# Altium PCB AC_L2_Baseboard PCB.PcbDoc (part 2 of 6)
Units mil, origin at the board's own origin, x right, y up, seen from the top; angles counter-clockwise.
Board outline 7290 x 7055 mil, 4 copper layers (Top Layer, Layer 1, Layer 2, Bottom Layer), stack 70.356 mil thick; 510 components, 285 nets, 1364 pads, 522 vias.
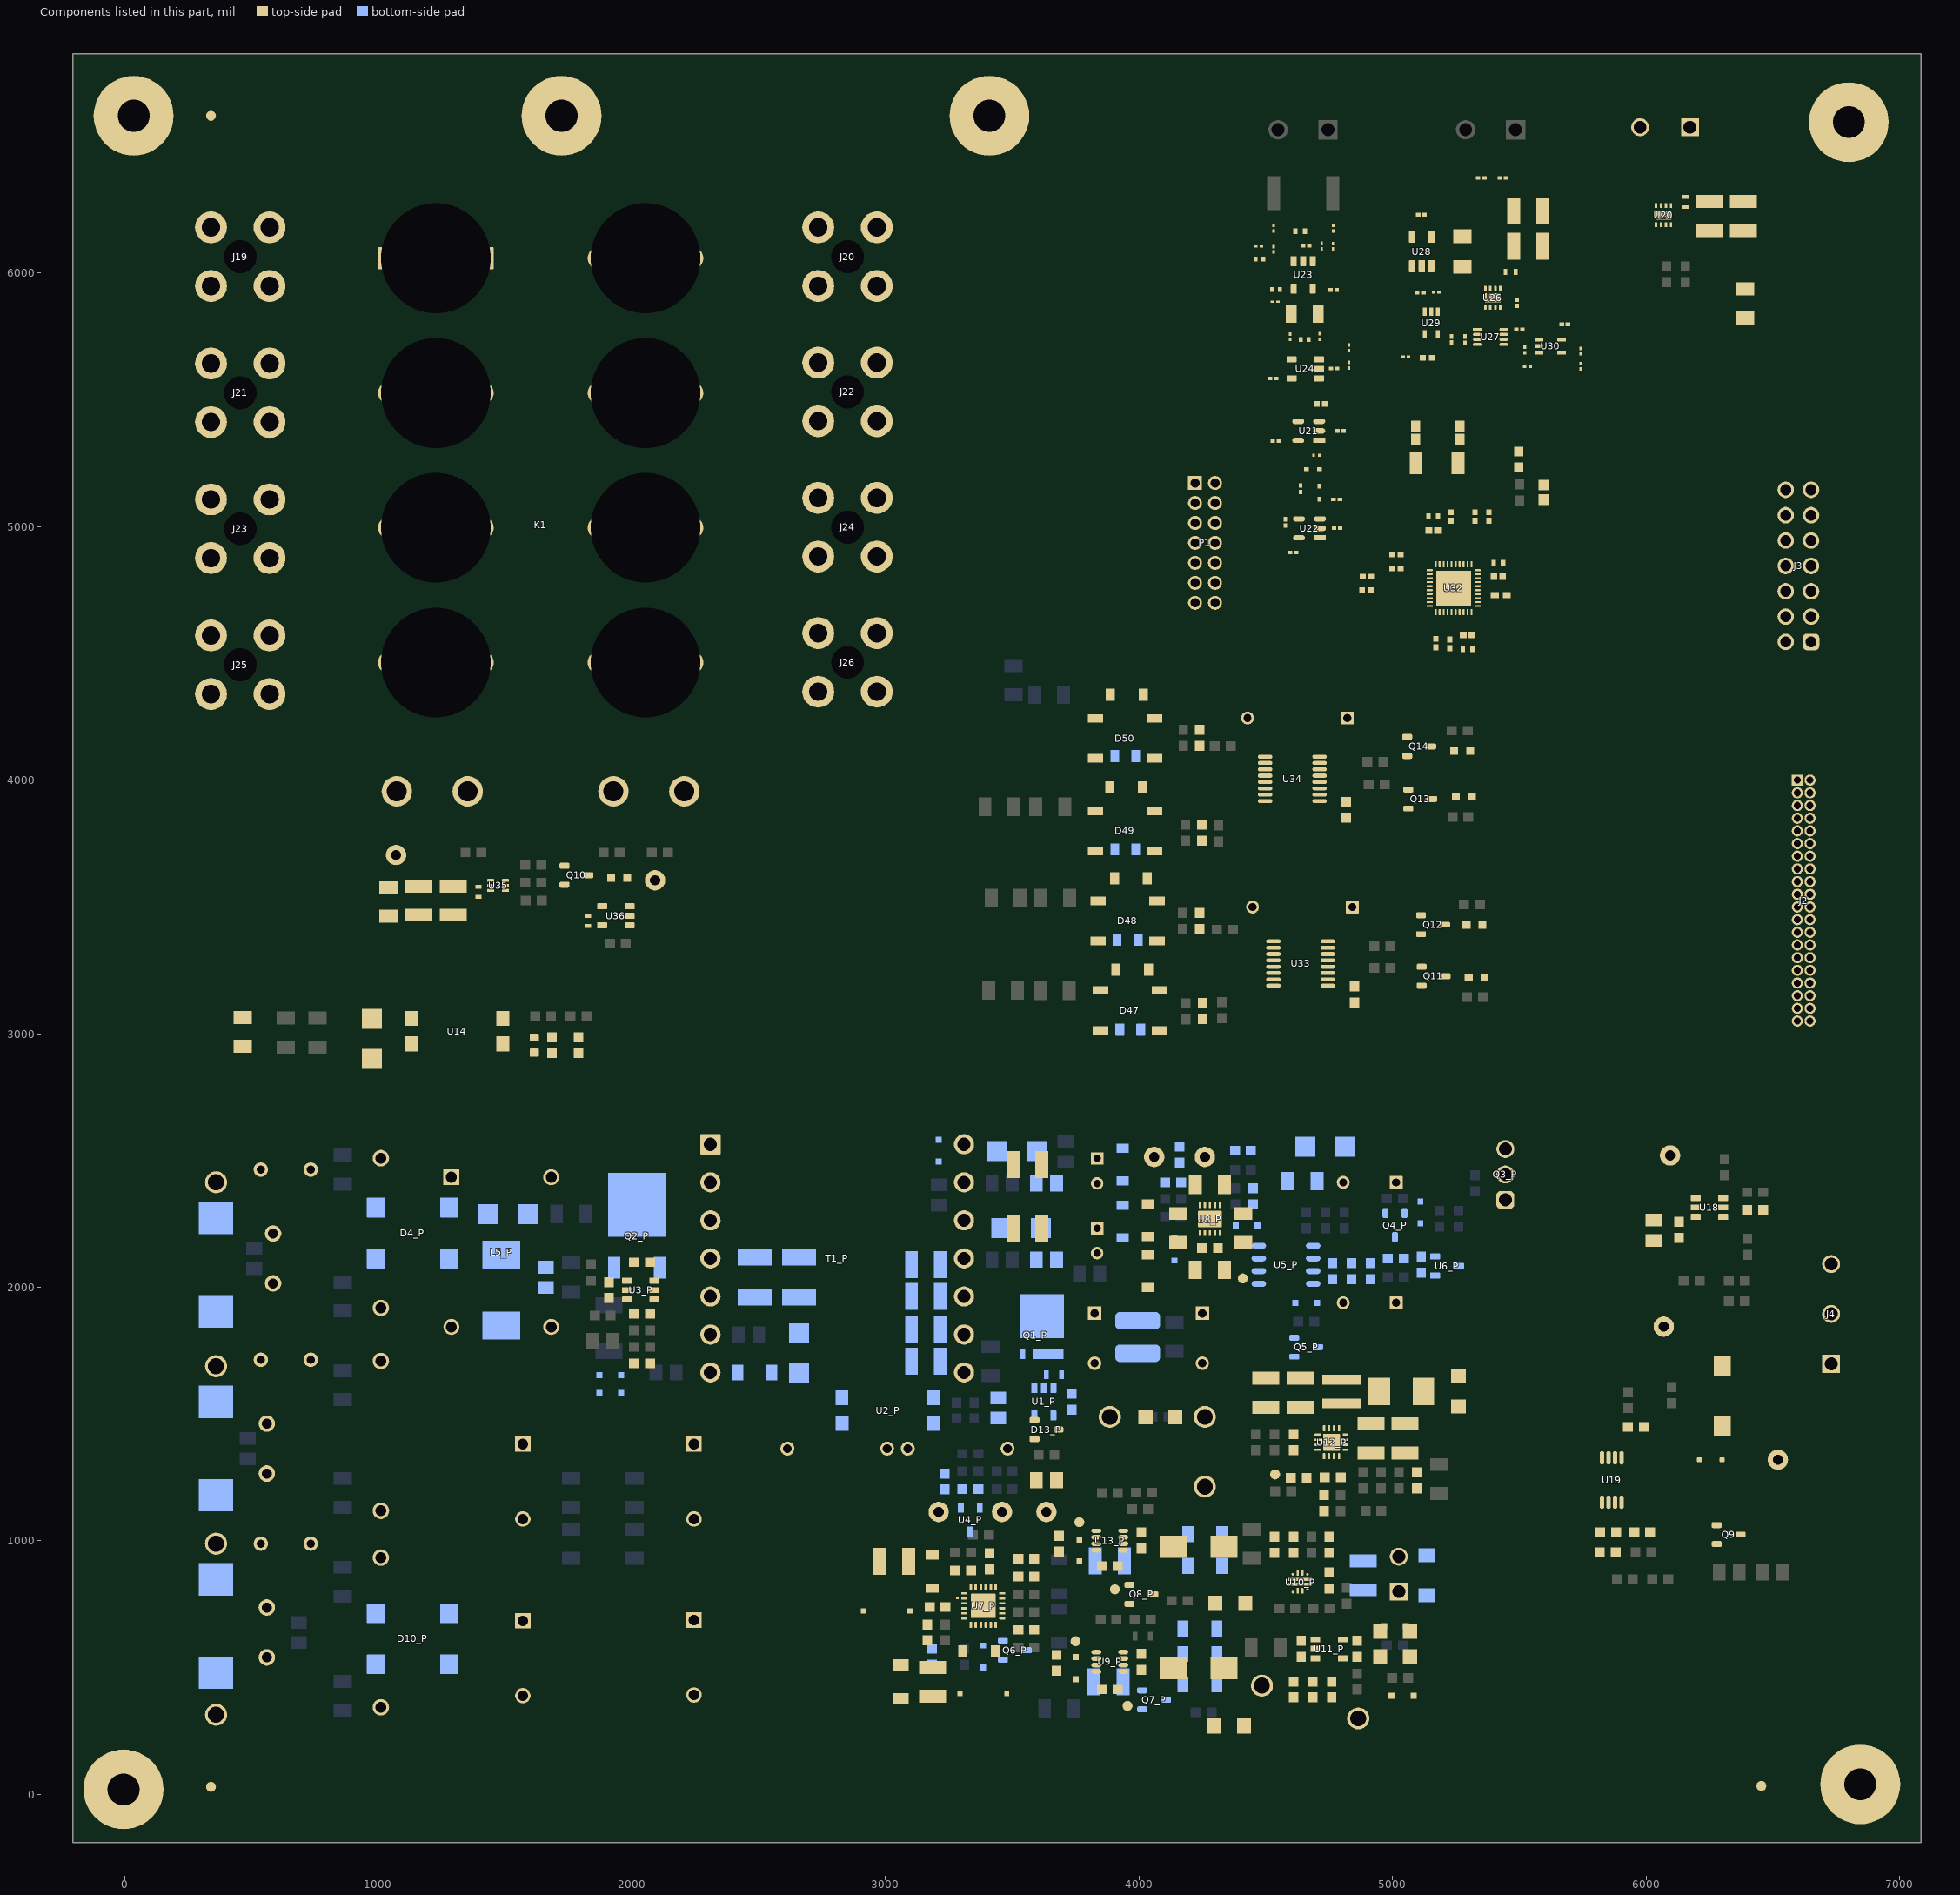
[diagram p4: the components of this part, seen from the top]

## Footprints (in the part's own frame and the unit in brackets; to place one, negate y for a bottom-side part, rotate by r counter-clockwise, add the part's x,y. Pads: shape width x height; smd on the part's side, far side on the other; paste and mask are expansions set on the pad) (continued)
B32672P_1800x850x1450 [mm] "TH, 2-Leads, Body 18x8.5mm, PinSpacing 15mm"
  round 1.65 hole 1.1: 1(-7.5,0) 2(7.5,0)
  silkscreen extent -9,-4.25 9,4.25, body extent -9,-4.25 9,4.25, height 14.5
CAPC1005X56X25NL10T15 [mm] "Chip Capacitor, 2-Leads, Body 1.00x0.50mm, IPC Medium Density"
  rect 0.68x0.64 smd: 1(-0.44,0) 2(0.44,0)
  body extent -0.55,-0.3 0.55,0.3, height 0.56
CE_Mark_5mm [mil] "Minimum text height for CE Mark"
  silkscreen extent -138,-98 138,98
Chemi-Con_630X1100 [mm] "TH, 2-Leads, Dia 6.3mm, Pin Spacing 2.5mm"
  rect 1.25x1.25 hole 0.75: 1(-1.25,0)
  round 1.25 hole 0.75: 2(1.25,0)
  silkscreen extent -3.4,-3.4 3.4,3.4, body extent -3.4,-3.4 3.41,3.4, height 12.51
Chemi-Con_1000x2000 [mm] "TH, 2-Leads, Body 10x20mm, Pin Spacing 5mm"
  rect 1.35x1.35 hole 0.85: 1(-2.5,0)
  round 1.35 hole 0.85: 2(2.5,0)
  silkscreen extent -5.25,-5.25 5.25,5.25, body extent -5.25,-5.25 5.25,5.25, height 21.5
D0008A_N [mm] "SOIC, 8-Leads, Body 4.9x3.9mm, Pitch 1.27mm, IPC Medium Density"
  oval 1.45x0.6 smd: 1(-2.725,1.905) 2(-2.725,0.635) 3(-2.725,-0.635) 4(-2.725,-1.905) 5(2.725,-1.905) 6(2.725,-0.635) 7(2.725,0.635) 8(2.725,1.905)
  silkscreen extent -3.3,-2.5 0.9,2.5, body extent -3,-2.45 3,2.45, height 1.63
DBQ0016A_N [mm] "SOP, 16-Leads, Body 4.9x3.9mm, Pitch 0.635mm, IPC Medium Density"
  oval 1.45x0.4 smd: 1(-2.725,2.222) 2(-2.725,1.587) 3(-2.725,0.952) 4(-2.725,0.317) 5(-2.725,-0.318) 6(-2.725,-0.953) 7(-2.725,-1.588) 8(-2.725,-2.223) 9(2.725,-2.222) 10(2.725,-1.587) 11(2.725,-0.952) 12(2.725,-0.317) 13(2.725,0.318) 14(2.725,0.953) 15(2.725,1.588) 16(2.725,2.223)
  silkscreen extent -3.35,-2.5 1.1,2.68, body extent -3.01,-2.45 3.01,2.45, height 1.63
DBV0005A_M [mm] "SOT23, 5-Leads, Body 2.9x1.6mm, Pitch 0.95mm, Lead Span 2.8mm, IPC Low Density"
  rrect15% 1.2x0.65 smd: 1(-1.475,0.95) 2(-1.475,0) 3(-1.475,-0.95) 4(1.475,-0.95) 5(1.475,0.95)
  silkscreen extent -1.63,-1.55 0.38,1.55, body extent -1.42,-1.46 1.42,1.46, height 1.09
DBV0005A_N [mm] "SOT23, 5-Leads, Body 2.9x1.6mm, Pitch 0.95mm, Lead Span 2.8mm, IPC Medium Density"
  rrect17% 1x0.6 smd: 1(-1.375,0.95) 2(-1.375,0) 3(-1.375,-0.95) 4(1.375,-0.95) 5(1.375,0.95)
  silkscreen extent -0.25,-1.55 0.25,1.55, body extent -1.42,-1.46 1.42,1.46, height 1.09
DBV0006A_N [mm] "SOT23, 6-Leads, Body 2.9x1.6mm, Pitch 0.95mm, Lead Span 2.8mm, IPC Medium Density"
  rrect17% 1x0.6 smd: 1(-1.375,0.95) 2(-1.375,0) 3(-1.375,-0.95) 4(1.375,-0.95) 5(1.375,0) 6(1.375,0.95)
  silkscreen extent -1.68,-1.55 0.5,1.55, body extent -1.42,-1.46 1.42,1.46, height 1.12
DBZ0003A_N [mm] "SOT23, 3-Leads, Body 2.9x1.3mm, Pitch 0.95mm, Lead Span 2.4mm, IPC Medium Density"
  rrect17% 1x0.6 smd: 1(-1.2,0.95) 2(-1.2,-0.95) 3(1.2,0)
  silkscreen extent 0.2,-1.5 0.7,1.5, body extent -1.26,-1.46 1.26,1.46, height 0.98
DCK0005A_N [mm] "SOT353, 5-Leads, Body 2x1.3mm, Pitch 0.65mm, Lead Span 2.1mm, IPC Medium Density"
  rrect25% 0.85x0.4 smd: 1(-1.125,0.65) 2(-1.125,0) 3(-1.125,-0.65) 4(1.125,-0.65) 5(1.125,0.65)
  silkscreen extent -1.48,-1.02 0.55,1.1, body extent -1.14,-1 1.14,1, height 0.95
DDF0008A_N [mm] "SOT-23-THN-8, IPC Medium Density"
  oval 1x0.45 smd: 1(-1.35,0.975) 2(-1.35,0.325) 3(-1.35,-0.325) 4(-1.35,-0.975) 5(1.35,-0.975) 6(1.35,-0.325) 7(1.35,0.325) 8(1.35,0.975)
  body extent -1.41,-1.45 1.41,1.45, height 0.9
DGK0008A_N [mm] "TSOP, 8-Leads, Body 3x3mm, Pitch 0.65mm, IPC Medium Density"
  oval 1.35x0.45 smd: 1(-2.225,0.975) 2(-2.225,0.325) 3(-2.225,-0.325) 4(-2.225,-0.975) 5(2.225,-0.975) 6(2.225,-0.325) 7(2.225,0.325) 8(2.225,0.975)
  silkscreen extent -2.75,-1.55 0.95,1.55, body extent -2.45,-1.5 2.45,1.5, height 0.96
DRL0006A-MFG [mm]
  rrect33% 0.67x0.3 smd paste+0 mask+0: 1(-0.74,0.5) 2(-0.74,0) 3(-0.74,-0.5) 4(0.74,-0.5) 5(0.74,0) 6(0.74,0.5)
  silkscreen extent -1.9,-1.05 0.65,1.05, body extent -1.17,-1.1 1.17,1.1, height 0.25
DSC0010J [mm] "WSON-10"
  rrect42% 0.6x0.24 smd: 1(-1.4,1) 2(-1.4,0.5) 3(-1.4,0) 4(-1.4,-0.5) 5(-1.4,-1) 6(1.4,-1) 7(1.4,-0.5) 8(1.4,0) 9(1.4,0.5) 10(1.4,1)
  rrect12% 1.65x2.4 smd paste-1 mask-2: 11(0,0)
  Top Layer region: -0.375,-1.65 -0.375,-1.2 -0.775,-1.2 -0.794,-1.196 -0.81,-1.185 -0.821,-1.169 -0.825,-1.15 -0.825,-1.15 -0.825,1.15 -0.821,1.169 -0.81,1.185 -0.794,1.196 -0.775,1.2 -0.775,1.2 -0.375,1.2 -0.375,1.65 -0.371,1.669 -0.36,1.685 -0.344,1.696 -0.325,1.7 -0.325,1.7 -0.325,1.7 -0.175,1.7 -0.175,1.7 -0.156,1.696 -0.14,1.685 -0.129,1.669 -0.125,1.65 -0.125,1.65 -0.125,1.2 0.125,1.2 0.125,1.65 0.129,1.669 0.14,1.685 0.156,1.696 0.175,1.7 0.175,1.7 0.175,1.7 0.325,1.7 0.325,1.7 0.344,1.696 0.36,1.685 0.371,1.669 0.375,1.65 0.375,1.65 0.375,1.2 0.775,1.2 0.794,1.196 0.81,1.185 0.821,1.169 0.825,1.15 0.825,1.15 0.825,-1.15 0.821,-1.169 0.81,-1.185 0.794,-1.196 0.775,-1.2 0.775,-1.2 0.375,-1.2 0.375,-1.65 0.371,-1.669 0.36,-1.685 0.344,-1.696 0.325,-1.7 0.325,-1.7 0.175,-1.7 0.156,-1.696 0.14,-1.685 0.129,-1.669 0.125,-1.65 0.125,-1.65 0.125,-1.2 -0.125,-1.2 -0.125,-1.65 -0.129,-1.669 -0.14,-1.685 -0.156,-1.696 -0.175,-1.7 -0.175,-1.7 -0.325,-1.7 -0.344,-1.696 -0.36,-1.685 -0.371,-1.669 -0.375,-1.65
  body extent -1.5,-1.5 1.5,1.5, height 0.8
DSG0008A-MFG [mm]
  rrect40% 0.5x0.25 smd paste+0 mask+0: 1(-0.95,0.75) 2(-0.95,0.25) 3(-0.95,-0.25) 4(-0.95,-0.75) 5(0.95,-0.75) 6(0.95,-0.25) 7(0.95,0.25) 8(0.95,0.75)
  rrect11% 0.9x1.6 smd paste-1000 mask+0: 9(0,0)
  silkscreen extent -1.87,-1.39 1,1.4, body extent -1.3,-1.15 1.3,1.15, height 0.25
FCC_disclaimer [mil]
Fiducial10-20 [mm]
  round 1 smd mask+0.5: 1(0,0)
  Top Layer keep-out circle w1.178: c0,0 r0.5
FP-502-01-MFG [mm]
  rect 0.48x0.4 smd paste+0 mask+0: 1(-0.66,0) 2(0.66,0)
  silkscreen extent -1.63,-0.45 0.05,0.45, body extent -1,-0.55 1,0.55, height 0.25
FP-750320029_PTH14_32MM25_27MM05-MFG [mm]
  rrect5% 2.02x2.02 hole 1.32 paste-1000 mask+0: 1(-12.7,11.43)
  round 2.02 hole 1.32 paste-1000 mask+0: 2(-12.7,7.62) 3(-12.7,3.81) 4(-12.7,0) 5(-12.7,-3.81) 6(-12.7,-7.62) 7(-12.7,-11.43) 8(12.7,-11.43) 9(12.7,-7.62) 10(12.7,-3.81) 11(12.7,0) 12(12.7,3.81) 13(12.7,7.62) 14(12.7,11.43)
  silkscreen extent -16.85,-13.52 16.12,13.52, body extent -16.22,-13.62 16.22,13.62, height 0.25
FP-ABS10-MFG [mm]
  rect 1.3x2.2 smd paste+0 mask+0: 1(-2.1,0) 2(2.1,0)
  silkscreen extent -1.07,-0.95 1.07,0.95, body extent -2.85,-1.2 2.85,1.2, height 0.25
FP-AC0402-0_37-IPC_B [mil]
  rect 24.23x22.54 smd paste+0 mask+0: 1(-16.87,0) 2(16.87,0)
  silkscreen extent -29,-27 29,27, body extent -35,-17 35,17, height 10
FP-AHER4191_PTH_RELAY_35MM0_58MM0-MFG [mm]
  rrect5% 2.2x11.6 hole 11 slot 1.6 at 0 deg paste-1000 mask+0: 1(26.5,10.5)
  rrect100% 2.2x11.6 hole 11 slot 1.6 at 0 deg paste-1000 mask+0: 2(13,10.5) 3(-0.5,10.5) 4(-14,10.5) 9(-14,-10.5) 10(-0.5,-10.5) 11(13,-10.5) 12(26.5,-10.5)
  round 3.05 hole 2 paste-1000 mask+0: 5(-26.9,14.4) 6(-26.9,7.3) 7(-26.9,-7.3) 8(-26.9,-14.4)
  silkscreen extent -29.25,-17.75 29.97,17.75, body extent -29.35,-17.85 29.35,17.85, height 0.25
FP-AQ4023-01FTG-C_SOD323-MFG [mm]
  rrect22% 0.49x0.45 smd paste+0 mask+0: 1(-1.14,0) 2(1.14,0)
  silkscreen extent -0.9,-0.7 0.9,0.7, body extent -1.49,-0.8 1.49,0.8, height 0.25
FP-BSC220N20NSFDATMA1_TSON-8-MFG [mm]
  rrect10% 3.08x1 smd paste-1000 mask-1000: 1-2-3(-0.635,-2.75)
  rrect19% 0.54x1 smd paste-1000 mask+0: 4(1.905,-2.75)
  rrect2% 4.45x4.4 smd paste-1000 mask-1000: 5-6-7-8(0,1.05)
  silkscreen extent -2.5,-4.02 2.5,-1.53, body extent -2.5,-3.01 2.5,3.01, height 1.1
FP-C0201-AB-MFG [mm]
  rect 0.36x0.32 smd paste+0 mask+0: 1(-0.28,0) 2(0.28,0)
  silkscreen extent -0.3,-0.55 0.3,0.55
FP-C0603-030-0_03-MFG [mm]
  rect 0.25x0.3 smd paste+0 mask+0: 1(-0.275,0) 2(0.275,0)
  silkscreen extent -0.32,-0.53 0.32,0.53, body extent -0.5,-0.27 0.5,0.27, height 0.25
FP-C1608-080-0_1-IPC_B [mil]
  rect 44.53x35.91 smd paste+0 mask+0: 1(-25.22,0) 2(25.22,0)
  silkscreen extent -47,-34 47,34, body extent -57,-28 57,28, height 10
FP-CC0603KRX7R7BB224_0603-MFG [mm]
  rrect13% 0.8x0.9 smd paste+0 mask+0: 1(-0.75,0) 2(0.75,0)
  silkscreen extent -0.85,-0.85 0.85,0.85, body extent -1.43,-0.82 1.43,0.82, height 0.25
FP-CRCW1206-e3-IPC_A [mil]
  rect 53.39x73.16 smd paste+0 mask+0: 1(-60.08,0) 2(60.08,0)
  silkscreen extent -19,-31 19,31, body extent -106,-56 106,56, height 10
FP-DBV0005A-IPC_C [mm]
  rect 1.205x0.532 smd paste+0 mask+0: 1(-1.05,0.95)
  rrect100% 1.205x0.532 smd paste+0 mask+0: 2(-1.05,0) 3(-1.05,-0.95) 4(1.05,-0.95) 5(1.05,0.95)
  silkscreen extent -2.45,-1.45 0.05,1.45, body extent -1.75,-1.55 1.75,1.55, height 0.25
FP-DCU0008A-IPC_C [mm]
  rect 0.86x0.297 smd paste+0 mask+0: 1(-1.326,0.75)
  rrect100% 0.86x0.297 smd paste+0 mask+0: 2(-1.326,0.25) 3(-1.326,-0.25) 4(-1.326,-0.75) 5(1.326,-0.75) 6(1.326,-0.25) 7(1.326,0.25) 8(1.326,0.75)
  silkscreen extent -2.46,-1 0.4,1, body extent -1.86,-1.1 1.86,1.1, height 0.25
FP-ERA3A-IPC_B [mil]
  rect 41.53x39.61 smd paste+0 mask+0: 1(-28.57,0) 2(28.57,0)
  silkscreen extent -49,-36 49,36, body extent -59,-30 59,30, height 10
FP-FTSH-120-01-L-D_HDR40-MFG [mm]
  rrect9% 1.12x1.12 hole 0.71 paste-1000 mask+0: 1(-12.065,-0.635)
  round 1.12 hole 0.71 paste-1000 mask+0: 2(-12.065,0.635) 3(-10.795,-0.635) 4(-10.795,0.635) 5(-9.525,-0.635) 6(-9.525,0.635) 7(-8.255,-0.635) 8(-8.255,0.635) 9(-6.985,-0.635) 10(-6.985,0.635) 11(-5.715,-0.635) 12(-5.715,0.635) 13(-4.445,-0.635) 14(-4.445,0.635) 15(-3.175,-0.635) 16(-3.175,0.635) 17(-1.905,-0.635) 18(-1.905,0.635) 19(-0.635,-0.635) 20(-0.635,0.635) 21(0.635,-0.635) 22(0.635,0.635) 23(1.905,-0.635) 24(1.905,0.635) 25(3.175,-0.635) 26(3.175,0.635) 27(4.445,-0.635) 28(4.445,0.635) 29(5.715,-0.635) 30(5.715,0.635) 31(6.985,-0.635) 32(6.985,0.635) 33(8.255,-0.635) 34(8.255,0.635) 35(9.525,-0.635) 36(9.525,0.635) 37(10.795,-0.635) 38(10.795,0.635) 39(12.065,-0.635) 40(12.065,0.635)
  silkscreen extent -12.77,-2.37 12.77,1.78, body extent -12.87,-1.88 12.87,1.88, height 0.25
FP-GRM155-0_1-MFG [mm]
  rect 0.4x0.5 smd paste+0 mask+0: 1(-0.4,0) 2(0.4,0)
  silkscreen extent -0.53,-0.65 0.53,0.65, body extent -0.7,-0.38 0.7,0.38, height 0.25
FP-GRM155-0_2-MFG [mm]
  rect 0.45x0.6 smd paste+0 mask+0: 1(-0.475,0) 2(0.475,0)
  silkscreen extent -0.6,-0.64 0.6,0.65, body extent -0.8,-0.45 0.8,0.45, height 0.25
FP-GRT033-0_03-IPC_B [mil]
  rect 17.88x14.28 smd paste+0 mask+0: 1(-11.98,0) 2(11.98,0)
  silkscreen extent -21,-23 21,23, body extent -27,-13 27,13, height 10
FP-IPD95R2K0P7ATMA1_DPAK-MFG [mm]
  rrect8% 1.2x2.2 smd paste-1000 mask+0: 1(-2.28,-5.12) 3(2.28,-5.12)
  rrect2% 5.8x6.4 smd paste-1000 mask+0: 4(0,1.18)
  silkscreen extent -3.35,-3.1 3.35,3.1, body extent -3.27,-5.79 3.27,4.15, height 2.42
FP-PHVL-3R9V255-R_RADIAL-MFG [mm]
  rrect8% 1.3x1.3 hole 0.8 paste-1000 mask+0: 1(-2.65,0)
  round 1.3 hole 0.8 paste-1000 mask+0: 2(2.65,0)
  silkscreen extent -10.9,-5.75 10.9,5.75, body extent -11,-5.85 11,5.85, height 0.25
FP-Q07E1D471KN0B0S0N0_RADIAL-MFG [mm]
  rrect8% 1.3x1.3 hole 0.8 paste-1000 mask+0: 1(-5,0)
  round 1.3 hole 0.8 paste-1000 mask+0: 2(5,0)
  silkscreen extent -3.5,-2.5 3.5,2.5, body extent -5.75,-2.6 5.75,2.6, height 0.25
FP-RC0805FR-070RL_0805-MFG [mm]
  rrect11% 0.9x1.2 smd paste+0 mask+0: 1(-1.05,0) 2(1.05,0)
  silkscreen extent -0.23,-0.67 0.23,0.67, body extent -1,-0.63 1,0.63, height 0.6
FP-RG1005-IPC_B [mil]
  rect 23.18x22.54 smd paste+0 mask+0: 1(-18.25,0) 2(18.25,0)
  silkscreen extent -30,-27 30,27, body extent -36,-17 36,17, height 10
FUSE_0443 [mm] "LITTELFUSE"
  rect 3.25x3.43 smd: 1(-4.675,0) 2(4.675,0)
  silkscreen extent -2.7,-1.7 2.7,1.7, body extent -5.05,-1.56 5.05,1.56, height 3.12
HW_1600x2500 [mm] "TH, 2-Leads, Dia 16mm, Pin Spacing 7.5mm"
  rect 1.55x1.55 hole 1.05: 1(-3.75,0)
  round 1.55 hole 1.05: 2(3.75,0)
  silkscreen extent -8.25,-8.25 8.25,8.25, body extent -8.19,-8.24 8.23,8.24, height 27.01
IEC_HighVoltage_Medium [mil]
  silkscreen extent -217,-176 217,200
Keystone5000 [mil] "For Keystone 500x miniature loop terminals"
  round 80 hole 40: 1(0,0)
  silkscreen extent -52,-52 52,52, body extent -49,-49 49,49, height 182
Keystone5001 [mil] "For Keystone 500x miniature loop terminals"
  round 80 hole 40: 1(0,0)
  silkscreen extent -52,-52 52,52, body extent -49,-49 49,49, height 182
Keystone5003 [mil] "For Keystone 500x miniature loop terminals"
  round 80 hole 40: 1(0,0)
  silkscreen extent -52,-52 52,52, body extent -49,-49 49,49, height 182
Keystone5010 [mil] "Keystone Multipurpose loops"
  round 87 hole 63: 1(0,0)
  silkscreen extent -70,-70 70,70, body extent -63,-63 63,62, height 319
Keystone5011 [mil] "Keystone Multipurpose loops"
  round 87 hole 63: 1(0,0)
  silkscreen extent -70,-70 70,70, body extent -63,-63 63,62, height 319
Keystone5012 [mil] "Keystone Multipurpose loops"
  round 87 hole 63: 1(0,0)
  silkscreen extent -70,-70 70,70, body extent -63,-63 63,62, height 319
KX_1000x700 [mm] "TH, 2-Leads, Dia 10mm, Lead Spacing 10mm"
  round 1.4 hole 0.9: 1(-5,0) 2(5,0)
  silkscreen extent -5,-3.5 5,3.5, body extent -5.32,-3.5 5.33,3.5, height 12.99
Label_650x200 [mil] "Thermal Transfer Label"
  round 1 on Mech14: 0(0,0)
  silkscreen extent -325,-100 325,100, body extent -325,-100 325,100, height 1
MICRODIP_4 [mm] "FAIRCHILD"
  rect 1.55x0.85 smd: 1(-2.95,2) 2(-2.95,-2) 3(2.95,-2) 4(2.95,2)
  silkscreen extent -2.62,-2.6 2.3,2.6, body extent -3.4,-2.57 3.4,2.57, height 1.45
MOLEX-87831-1420_V [mm] "Connector, 14-Leads, Body 16.65x6.3mm, Pitch 2mm"
  rect 1.4x1.4 hole 0.9: 1(-6,-1)
  round 1.4 hole 0.9: 2(-6,1) 3(-4,-1) 4(-4,1) 5(-2,-1) 6(-2,1) 7(0,-1) 8(0,1) 9(2,-1) 10(2,1) 11(4,-1) 12(4,1) 13(6,-1) 14(6,1)
  silkscreen extent -8.32,-3.92 8.32,3.15, body extent -8.32,-3.15 8.33,3.15, height 6.2
N04C [mm] "FAIRCHILD"
  rect 1.3x1.5 smd mask+0.065: 1(-4.587,1.27) 2(-4.612,-1.27) 3(4.588,-1.27) 4(4.613,1.27)
  silkscreen extent -3.56,-2.3 3.56,2.72, body extent -5.08,-2.3 5.08,2.29, height 3.87
Net-Tie_10mil [mil] "10mil net tie, no solder mask opening, no solder paste"
  rect 10x10 smd paste-5 mask-5: 1(-10,0) 2(10,0)
  Top Layer region: -6,5 6,5 6,-5 -6,-5
Net-Tie_0805_HV_NoOverlay [mil] "0805_HV pads tied by 10mil copper trace which can be cut.  An 0805 part can be placed on pads."
  rect 50x63 smd paste-25: 1(-40,0) 2(40,0)
  Top Layer lines w10: 16,0 -16,0
  Top Layer keep-out lines w1: 22,-30.91 22,30.91 ; 14.96,-30.91 -14.96,-30.91 ; -22,-30.91 -22,30.91 ; 14.96,30.91 -14.96,30.91
"NY PMS 440 0025 PH" [mm] "4-40 nylon screw and mounting hole"
  round 8 hole 3.2: 1(0,0)
  body extent -3.3,-3.3 3.3,3.3, height 2.69
RESC0603X28X15LL05T05 [mm] "Chip Resistor, 2-Leads, Body 0.60x0.30mm, IPC High Density"
  rect 0.35x0.25 smd: 1(-0.275,0) 2(0.275,0)
  body extent -0.33,-0.17 0.32,0.18, height 0.28
RESC0603X28X15NL05T05 [mm] "Chip Resistor, 2-Leads, Body 0.60x0.30mm, IPC Medium Density"
  rect 0.45x0.35 smd: 1(-0.325,0) 2(0.325,0)
  body extent -0.33,-0.17 0.33,0.18, height 0.28
RESC1005X40X25NL05T10 [mm] "Chip Resistor, 2-Leads, Body 1.00x0.50mm, IPC Medium Density"
  rect 0.6x0.55 smd: 1(-0.425,0) 2(0.425,0)
  body extent -0.53,-0.27 0.53,0.28, height 0.4
RGE0024B [mm] "QFN, 24-Leads, Body 4x4mm, Pitch 0.5mm, Thermal Pad 2.45x2.45mm, TI Recommended"
  rrect40% 0.6x0.25 smd: 1(-1.9,1.25) 2(-1.9,0.75) 3(-1.9,0.25) 4(-1.9,-0.25) 5(-1.9,-0.75) 6(-1.9,-1.25) 13(1.9,-1.25) 14(1.9,-0.75) 15(1.9,-0.25) 16(1.9,0.25) 17(1.9,0.75) 18(1.9,1.25)
  rrect40% 0.25x0.6 smd: 7(-1.25,-1.9) 8(-0.75,-1.9) 9(-0.25,-1.9) 10(0.25,-1.9) 11(0.75,-1.9) 12(1.25,-1.9) 19(1.25,1.9) 20(0.75,1.9) 21(0.25,1.9) 22(-0.25,1.9) 23(-0.75,1.9) 24(-1.25,1.9)
  rrect9% 1.08x1.08 on Top Paste: 25(-0.64,-0.64) 25(-0.64,0.64) 25(0.64,-0.64) 25(0.64,0.64)
  rrect4% 2.45x2.45 smd paste-1.225: 25(0,0)
  silkscreen extent -2.22,-2.22 2.22,2.22, body extent -2,-2 2,2, height 1
RPW0010A-MFG [mm]
  round 0.27 smd paste-1000 mask+0: 1(-1.05,0.7) 10(0.75,0.7)
  rrect40% 0.6x0.25 smd paste+0 mask+0: 2(-0.9,0.225) 3(-0.9,-0.225) 8(0.9,-0.225) 9(0.9,0.225)
  round 0.255 smd paste-1000 mask+0: 4(-0.75,-0.75) 7(0.75,-0.75)
  rrect33% 0.3x2.4 smd paste-1000 mask+0: 5(-0.25,0) 6(0.25,0)
  Top Layer region: -0.85,0.85 -0.85,1.15 -0.843,1.175 -0.825,1.193 -0.8,1.2 -0.8,1.2 -0.65,1.2 -0.631,1.196 -0.615,1.185 -0.604,1.169 -0.6,1.15 -0.6,1.15 -0.6,0.6 -0.604,0.581 -0.615,0.565 -0.631,0.554 -0.65,0.55 -0.65,0.55 -1.15,0.55 -1.169,0.554 -1.185,0.565 -1.196,0.581 -1.2,0.6 -1.2,0.6 -1.2,0.8 -1.193,0.825 -1.175,0.843 -1.15,0.85 -1.15,0.85
  Top Layer region: -0.85,-0.85 -0.85,-1.15 -0.846,-1.169 -0.835,-1.185 -0.819,-1.196 -0.8,-1.2 -0.8,-1.2 -0.65,-1.2 -0.631,-1.196 -0.615,-1.185 -0.604,-1.169 -0.6,-1.15 -0.6,-1.15 -0.6,-0.6 -0.604,-0.581 -0.615,-0.565 -0.631,-0.554 -0.65,-0.55 -0.65,-0.55 -1.15,-0.55 -1.169,-0.554 -1.185,-0.565 -1.196,-0.581 -1.2,-0.6 -1.2,-0.6 -1.2,-0.8 -1.196,-0.819 -1.185,-0.835 -1.169,-0.846 -1.15,-0.85 -1.15,-0.85
  Top Layer region: 0.85,-0.85 0.85,-1.15 0.846,-1.169 0.835,-1.185 0.819,-1.196 0.8,-1.2 0.8,-1.2 0.65,-1.2 0.631,-1.196 0.615,-1.185 0.604,-1.169 0.6,-1.15 0.6,-1.15 0.6,-0.6 0.604,-0.581 0.615,-0.565 0.631,-0.554 0.65,-0.55 0.65,-0.55 1.15,-0.55 1.169,-0.554 1.185,-0.565 1.196,-0.581 1.2,-0.6 1.2,-0.6 1.2,-0.8 1.196,-0.819 1.185,-0.835 1.169,-0.846 1.15,-0.85 1.15,-0.85
  Top Layer region: 0.85,0.85 0.85,1.15 0.846,1.169 0.835,1.185 0.819,1.196 0.8,1.2 0.8,1.2 0.65,1.2 0.631,1.196 0.615,1.185 0.604,1.169 0.6,1.15 0.6,1.15 0.6,0.6 0.604,0.581 0.615,0.565 0.631,0.554 0.65,0.55 0.65,0.55 1.15,0.55 1.169,0.554 1.185,0.565 1.196,0.581 1.2,0.6 1.2,0.6 1.2,0.8 1.196,0.819 1.185,0.835 1.169,0.846 1.15,0.85 1.15,0.85
  silkscreen extent -1.87,-1.58 1.05,1.58, body extent -1.3,-1.3 1.3,1.3, height 0.25
RSB0040B [mm] "WQFN-40"
  rrect50% 0.6x0.2 smd: 1(-2.4,1.8) 2(-2.4,1.4) 3(-2.4,1) 4(-2.4,0.6) 5(-2.4,0.2) 6(-2.4,-0.2) 7(-2.4,-0.6) 8(-2.4,-1) 9(-2.4,-1.4) 10(-2.4,-1.8) 21(2.4,-1.8) 22(2.4,-1.4) 23(2.4,-1) 24(2.4,-0.6) 25(2.4,-0.2) 26(2.4,0.2) 27(2.4,0.6) 28(2.4,1) 29(2.4,1.4) 30(2.4,1.8)
  rrect50% 0.2x0.6 smd: 11(-1.8,-2.4) 12(-1.4,-2.4) 13(-1,-2.4) 14(-0.6,-2.4) 15(-0.2,-2.4) 16(0.2,-2.4) 17(0.6,-2.4) 18(1,-2.4) 19(1.4,-2.4) 20(1.8,-2.4) 31(1.8,2.4) 32(1.4,2.4) 33(1,2.4) 34(0.6,2.4) 35(0.2,2.4) 36(-0.2,2.4) 37(-0.6,2.4) 38(-1,2.4) 39(-1.4,2.4) 40(-1.8,2.4)
  rrect3% 3.5x3.5 smd paste-1.75: 41(0,0)
  body extent -2.5,-2.5 2.5,2.5, height 0.8
RTE0016C_NV [mm] "Texas Insturments"
  rrect42% 0.6x0.24 smd: 1(-1.4,0.75) 2(-1.4,0.25) 3(-1.4,-0.25) 4(-1.4,-0.75) 9(1.4,-0.75) 10(1.4,-0.25) 11(1.4,0.25) 12(1.4,0.75)
  rrect42% 0.24x0.6 smd: 5(-0.75,-1.4) 6(-0.25,-1.4) 7(0.25,-1.4) 8(0.75,-1.4) 13(0.75,1.4) 14(0.25,1.4) 15(-0.25,1.4) 16(-0.75,1.4)
  rrect6% 1.55x1.55 on Top Paste: 17(0,0)
  rrect6% 1.68x1.68 smd paste-0.85: 17(0,0)
  silkscreen extent -1.72,-1.73 1.72,1.73, body extent -1.57,-1.57 1.58,1.58, height 0.81
S153 [mm] "EPCOS"
  round 1.45 hole 0.8: 1(-2.5,0) 2(2.5,0)
  silkscreen extent -4.2,-3 4.2,3, body extent -4.23,-3 4.23,3, height 12.99
SMA [mm] "Molded Diode, 2-Leads, Body 4.3x2.6mm, IPC Medium Density, based on OnSemi component dimensions and land pattern"
  rect 2x2 smd: 1(-2,0) 2(2,0)
  silkscreen extent -3.66,-1.57 2.79,1.57, body extent -2.6,-1.3 2.6,1.3, height 2.42
SMA_Bi [mm] "SMD, 2-Leads, Body 4.275x2.575mm"
  rect 1.4x1.64 smd: 1(-2.015,0) 2(2.015,0)
  silkscreen extent -2.3,-1.45 2.3,1.45, body extent -2.52,-1.45 2.52,1.45, height 2.65
SMB [mil] "Molded Diode, 2-Leads, Body 5.4x3.6mm, IPC Medium Density, based on OnSemi component dimensions"
  rect 85x107.99 smd: 1(-87.01,0) 2(87.01,0)
  silkscreen extent -155,-82 125,82, body extent -106,-71 106,71, height 91
SMC [mil] "Molded Diode, 2-Leads, Body 6.9x5.8mm, IPC Medium Density, based on OnSemi component dimensions and land patterns"
  rect 110x150 smd: 1(-140.49,0) 2(140.49,0)
  silkscreen extent -221,-123 189,124, body extent -156,-116 156,116, height 91
SOD-123 [mm] "On Semi recommended land pattern"
  rect 0.915x1.22 smd: 1(-1.637,0) 2(1.637,0)
  silkscreen extent -2.74,-1.17 2.03,1.17, body extent -1.93,-0.9 1.93,0.9, height 1.35
SOD-123FL [mm] "Copied from SOD-123"
  rect 0.915x1.22 smd: 1(-1.637,0) 2(1.637,0)
  silkscreen extent -2.74,-1.16 1.68,1.16, body extent -1.9,-0.9 1.9,0.9, height 1
SOD-323 [mm] "NXP recommended land pattern"
  rect 0.6x0.6 smd paste-0.05: 1(-1.1,0) 2(1.1,0)
  silkscreen extent -2.06,-0.86 1.53,0.86, body extent -1.3,-0.67 1.3,0.68, height 1.1
SOT-23 [mm] "SOT23, 3-Leads, Body 2.9x1.3mm, Pitch 0.95mm, Lead Span 2.5mm, IPC Medium Density"
  rrect50% 1x0.6 smd: 1(-1.2,0.95) 2(-1.2,-0.95) 3(1.2,0)
  silkscreen extent -1.63,-1.5 0.7,1.5, body extent -1.16,-1.45 1.21,1.45, height 1
TBS4 [mm] "Micro Commercial Components"
  rrect6% 1.8x2 smd: 1(-3.675,2.55) 2(-3.675,-2.55) 3(3.675,-2.55) 4(3.675,2.55)
  silkscreen extent -3.8,-3.45 3.8,3.45, body extent -4.3,-3.35 4.3,3.35, height 1.51
TO-220FP [mm] "FM, Body 10.4x4.6mm, Pitch 2.55mm"
  rrect50% 1.8x1.8 hole 1.3: 1(-2.55,0)
  round 1.8 hole 1.3: 2(0,0) 3(2.55,0)
  silkscreen extent -5.1,-1.5 5.08,3, body extent -5.09,-1.5 5.09,3, height 19.41
TP_SM_1MM [mm] "1mm Test Point, SMT"
  round 1 smd paste-0.5: 1(0,0)
WE-HC4 [mm] "Wurth Electronik recommended land pattern"
  rect 2.7x2.2 smd: 1(-2.55,0) 2(2.55,0)
  silkscreen extent -4.2,-4.2 4.2,4.2, body extent -3.65,-3.6 3.65,3.6, height 4
WE-PD2-S [mm] "WURTH"
  rrect50% 1.75x4.5 smd: 1(-1.625,0) 2(1.625,0)
  Top Layer region: -1.375,2.25 -0.75,2.25 -0.75,-2.25 -1.375,-2.25
  Top Layer region: 1.375,-2.25 0.75,-2.25 0.75,2.25 1.375,2.25
  silkscreen extent -0.4,-2.1 0.4,2.12, body extent -2.25,-2 2.25,2, height 3.18
WE-PD_7345_PlasticBase [mm] "SMD Inductor, 2-Leads, Body 7,3x7,3mm"
  rect 2x1.7 smd: 1(-3,0) 2(3,0)
  silkscreen extent -3.8,-3.8 3.8,3.8, body extent -3.65,-3.65 3.65,3.65, height 4.09
WE-TI_1014 [mm] "WURTH"
  round 1.65 hole 1: 1(-2.5,0) 2(2.5,0)
  silkscreen extent -5.3,-5.3 5.3,5.3, body extent -5.25,-5.25 5.25,5.25, height 14.5
WE-TPC-M1 [mm] "Wurth Elektronik recommended land pattern"
  rect 0.5x0.5 smd: 1(-2.35,0) 2(2.325,0)
  Top Layer region: -0.75,1.64 -1.005,1.504 -1.279,1.279 -1.504,1.005 -1.671,0.692 -1.774,0.353 -1.809,0 -1.774,-0.353 -1.671,-0.692 -1.504,-1.005 -1.279,-1.279 -1.005,-1.504 -0.75,-1.64 -0.75,-2.65 -2.75,-2.65 -2.75,2.65 -0.75,2.65
  Top Layer region: 0.75,1.64 1.005,1.504 1.279,1.279 1.504,1.005 1.671,0.692 1.774,0.353 1.809,0 1.774,-0.353 1.671,-0.692 1.504,-1.005 1.279,-1.279 1.005,-1.504 0.75,-1.64 0.75,-2.65 2.75,-2.65 2.75,2.65 0.75,2.65
  silkscreen extent -3,-3 3,3, body extent -2.5,-2.5 2.5,2.5, height 2
WEEE_Minimum [mil] "WEEElie bin"
  silkscreen extent -95,-172 99,104
WL-SMCW_GREEN [mm] "WURTH"
  rect 0.8x0.8 smd: 1(-0.8,0) 2(0.8,0)
  silkscreen extent -1.9,-0.8 1.2,0.8, body extent -0.85,-0.45 0.85,0.45, height 0.8
WL_SMCW_RED_1206 [mm] "SMD, 2-Leads, Body 3.2x1.6mm, Pitch 3mm"
  rect 1.4x1.5 smd: 1(-1.5,0) 2(1.5,0)
  silkscreen extent -2.9,-1.1 2.2,1.1, body extent -1.6,-0.85 1.6,0.85, height 0.78
Wurth_7446120047 [mm] "TH, 4-Leads, Body 18.5x13.5"
  rect 1.6x1.6 hole 1.1: 1(-5,7.5)
  round 1.6 hole 1.1: 2(5,7.5) 3(5,-7.5) 4(-5,-7.5)
  silkscreen extent -6.75,-9.25 6.75,9.75, body extent -6.74,-9.25 6.74,9.25, height 20.51
Wurth_61301421121 [mm] "Header, 2.54mm, 7x2, TH"
  rrect50% 1.65x1.65 hole 1.1: 1(-1.27,7.62)
  round 1.65 hole 1.1: 2(1.27,7.62) 3(-1.27,5.08) 4(1.27,5.08) 5(-1.27,2.54) 6(1.27,2.54) 7(-1.27,0) 8(1.27,0) 9(-1.27,-2.54) 10(1.27,-2.54) 11(-1.27,-5.08) 12(1.27,-5.08) 13(-1.27,-7.62) 14(1.27,-7.62)
  body extent -2.54,-8.89 2.54,8.89, height 8.55
Wurth_691101710002 [mm] "Terminal Block, 5 mm, 2x1, TH"
  rect 1.8x1.8 hole 1.3: 1(-2.5,0)
  round 1.8 hole 1.3: 2(2.5,0)
  silkscreen extent -5,-4.5 5.6,5, body extent -5.6,-4 5.6,5, height 12.5
Wurth_691101710003 [mm] "Terminal Block, 5 mm, 3x1, TH"
  rect 1.8x1.8 hole 1.3: 1(-5,0)
  round 1.8 hole 1.3: 2(0,0) 3(5,0)
  silkscreen extent -7.5,-4.5 8.1,5, body extent -8.1,-4 8.1,5, height 12.5
Wurth_691214110002 [mm] "Receptacle, 3.5mm, 2x1, TH"
  rect 1.8x1.8 hole 1.3: 1(-1.75,0)
  round 1.8 hole 1.3: 2(1.75,0)
  silkscreen extent -3.8,-3.4 3.5,4, body extent -3.9,-3.4 3.5,4, height 8.5
Wurth_WP-THRBU [mm] "Power Element Bush, M3, TH"
  round 3.2 hole 1.85: 1(-2.935,-2.935) 1(-2.935,2.935) 1(2.935,-2.935) 1(2.935,2.935)
  round 3.1 on Top Paste: ""(-2.935,-2.935) ""(-2.935,2.935) ""(2.935,-2.935) ""(2.935,2.935)
  round 3 hole 3.3 unplated mask+0.102: ""(0,0)
  silkscreen extent -3.5,-3.5 3.5,3.5, body extent -3.5,-3.5 3.5,3.5, height 3
XEL4030_310 [mm] "SMD, 2-Leads, Body 4x4mm, Pitch 2.37mm"
  rect 0.98x3.9 smd: 1(-1.185,0) 2(1.185,0)
  silkscreen extent -2.3,-2.3 2.3,2.3, body extent -2.15,-2.15 2.15,2.15, height 3.1

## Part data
C1_P C11_P: library part CMP-0008246-2, "CAP, CERM, 68 pF, 250 V, +/- 5%, C0G/NP0, 0805", Cap_Case=0805, Manufacturer=MuRata, Supplier Part Number 1=490-5540-1-ND, TempCo=C0G/NP0, Tolerance_%=5%, Value1=Unknown, Value2=250V, ValueDisplayed=68pF
C2_P C3_P: library part CMP-0009604-2, "CAP, CERM, 3300 pF, 300 V, +/- 20%, E, D10xT7mm", Cap_Case=10x7mm, Manufacturer=MuRata, Supplier Part Number 1=490-9516-1-ND, TempCo=E, Tolerance_%=20%, Value1=Unknown, Value2=300V, ValueDisplayed=3300pF
C4_P C12_P: library part CMP-0010399-1, "CAP, AL, 100 uF, 25 V, +/- 20%, TH", Cap_Case=6.3x11, Manufacturer=Wuerth, Tolerance_%=20%, Value1=Unknown, Value2=25V, ValueDisplayed=100uF
C5_P C10_P C21_P C22_P C23_P C24_P C43_P C54_P C64_P C74_P C79_P C80_P C83_P C84_P C87_P: library part CMP-0009224-2, "CAP, CERM, 22 uF, 25 V, +/- 20%, X5R, 1210", Cap_Case=1210, Manufacturer=Wuerth, TempCo=X5R, Tolerance_%=20%, Value1=Unknown, Value2=25V, ValueDisplayed=22uF
C6_P C7_P: library part CMP-0009326-2, "CAP, CERM, 0.1 uF, 1000 V, +/- 10%, X7R, 1812", Cap_Case=1812, Manufacturer=Kemet, Supplier Part Number 1=399-9854-1-ND, TempCo=X7R, Tolerance_%=10%, Value1=Unknown, Value2=1000V, ValueDisplayed=0.1uF
C8_P: library part CMP-0008251-2, "CAP, CERM, 1000 pF, 250 V, +/- 10%, X7R, 0805", Cap_Case=0805, Manufacturer=Wuerth, TempCo=X7R, Tolerance_%=10%, Value1=Unknown, Value2=250V, ValueDisplayed=1000pF
C9_P C15_P C20_P: library part CMP-0860409-1, "CAP, Film, 0.1 µF, 1000 VDC,+/- 10%, TH", Cap_Case=18x8.5x15mm, Manufacturer=Wuerth, Tolerance_%=10%, Value2=1KV, ValueDisplayed=0.1µF
C13_P C14_P C16_P C17_P: library part CMP-0009928-2, "CAP, AL, 68 uF, 400 V, +/- 20%, 410 mA @ 120 Hz, TH", Cap_Case=16x25mm, Manufacturer=Wuerth, Tolerance_%=20%, Value2=410mA@120Hz, ValueDisplayed=68uF
C18_P C29_P C32_P C37_P C40_P C41_P C42_P C51_P C55_P C63_P C65_P C70_P C82_P C85_P C88_P C92_P: library part CMP-0007044-5, "CAP, CERM, 0.1 uF, 50 V, +/- 10%, X7R, 0603", Cap_Case=0603, Manufacturer=Wuerth, TempCo=X7R, Tolerance_%=10%, Value1="0.0296 ohm", Value2=50V, ValueDisplayed=0.1uF
C19_P: library part CMP-0007499-4, "CAP, CERM, 2.2 uF, 16 V, +/- 10%, X7R, 0603", Cap_Case=0603, Manufacturer=MuRata, Supplier Part Number 1=81-GRM188Z71C225KE3D, TempCo=X7R, Tolerance_%=10%, Value1=Unknown, Value2=16V, ValueDisplayed=2.2uF
C25_P C26_P: library part CMP-0010412-1, "CAP, AL, 680 uF, 25 V, +/- 20%, TH", Cap_Case=10x20, Manufacturer=Wuerth, Tolerance_%=20%, Value1=Unknown, Value2=25V, ValueDisplayed=680uF
C27_P: library part CMP-0008236-2, "CAP, CERM, 100 pF, 250 V, +/- 5%, C0G/NP0, 0805", Cap_Case=0805, Manufacturer=MuRata, Supplier Part Number 1=490-5542-1-ND, TempCo=C0G/NP0, Tolerance_%=5%, Value1=Unknown, Value2=250V, ValueDisplayed=100pF
C28_P C76_P: library part CMP-0006897-4, "CAP, CERM, 2200 pF, 50 V, +/- 10%, X7R, 0603", Cap_Case=0603, Manufacturer=Wuerth, Supplier Part Number 1=1362428, TempCo=X7R, Tolerance_%=10%, Value1=Unknown, Value2=50V, ValueDisplayed=2200pF
C30_P: library part CMP-0086153-1, "CAP, CERM, 10 µF, 50 V,+/- 10%, X5R, 1206", Cap_Case=1206, Manufacturer=Wuerth, TempCo=X5R, Tolerance_%=10%, Value2=50V, ValueDisplayed=10µF
C31_P: library part CMP-0007870-2, "CAP, CERM, 4.7 uF, 25 V, +/- 20%, X5R, 0805", Cap_Case=0805, Manufacturer=Wuerth, TempCo=X5R, Tolerance_%=20%, Value1=Unknown, Value2=25V, ValueDisplayed=4.7uF
C33_P C44_P C47_P C53_P C61_P: library part CMP-0008821-2, "CAP, CERM, 10 uF, 50 V, +/- 10%, X7R, 1206", Cap_Case=1206, Manufacturer=Wuerth, TempCo=X7R, Tolerance_%=10%, Value1=Unknown, Value2=50V, ValueDisplayed=10uF
C34_P C36_P: library part CMP-0006840-4, "CAP, CERM, 100 pF, 50 V, +/- 5%, C0G/NP0, 0603", Cap_Case=0603, Manufacturer=Wuerth, TempCo=C0G/NP0, Tolerance_%=5%, Value1=Unknown, Value2=50V, ValueDisplayed=100pF
C35_P: library part CMP-0007049-4, "CAP, CERM, 0.047 uF, 50 V, +/- 10%, X7R, 0603", Cap_Case=0603, Manufacturer=Wuerth, TempCo=X7R, Tolerance_%=10%, Value1="0.049007 ohm", Value2=50V, ValueDisplayed=0.047uF
C38_P C39_P: library part CMP-0095175-1, "2.5 F (EDLC) Supercapacitor 3.9 V Radial 80mOhm 5000 Hrs @ 85°C", Digikey Part Number=283-PHVL-3R9V255-R-ND, Manufacturer="Cooper Bussmann", Mouser Part Number=504-PHVL-3R9V255-R, Operating Temperature Range="-40°C to +85°C", Tolerance_%=30%, ValueDisplayed=2.5F
C45_P C86_P: library part CMP-0006798-4, "CAP, CERM, 6.8 pF, 50 V, +/- 4%, C0G/NP0, 0603", Cap_Case=0603, Manufacturer=Wuerth, TempCo=C0G/NP0, Tolerance_%=4%, Value1="0.505 ohm", Value2=50V, ValueDisplayed=6.8pF
C46_P C56_P C58_P C60_P C71_P C75_P C93_P C94_P: library part CMP-0006854-4, "CAP, CERM, 0.01 uF, 50 V, +/- 10%, X7R, 0603", Cap_Case=0603, Manufacturer=Wuerth, TempCo=X7R, Tolerance_%=10%, Value1=0.01uF, Value2=50V
C48_P C59_P C69_P C72_P C73_P C81_P: library part CMP-0083856-1, "CAP, CERM, 1 µF, 25 V,+/- 10%, X7R, 0603", Cap_Case=0603, Manufacturer=Wuerth, TempCo=X7R, Tolerance_%=10%, Value2=25V, ValueDisplayed=1µF
C49_P: library part CMP-0007389-4, "CAP, CERM, 0.22 uF, 16 V, +/- 10%, X7R, 0603", Cap_Case=0603, Manufacturer=Wuerth, TempCo=X7R, Tolerance_%=10%, Value1=Unknown, Value2=16V, ValueDisplayed=0.22uF
C50_P C66_P C67_P C68_P C89_P C90_P: library part CMP-0064937-2, "CAP, CERM, 22 uF, 10 V,+/- 10%, X7R, 1206", Cap_Case=1206, Manufacturer="Wurth Elektronik", Supplier Part Number 1=732-7566-1-ND, TempCo=X7R, Tolerance_%=10%, Value1=Unknown, Value2=10V, ValueDisplayed=22uF
C52_P: library part CMP-0006795-4, "CAP, CERM, 5.6 pF, 50 V, +/- 5%, C0G/NP0, 0603", Cap_Case=0603, Manufacturer=Wuerth, Supplier Part Number 1=478-1160-1-ND, TempCo=C0G/NP0, Tolerance_%=5%, Value1="0.568 ohm", Value2=50V, ValueDisplayed=5.6pF
C57_P C62_P: library part CMP-0006835-4, "CAP, CERM, 4700 pF, 50 V, +/- 10%, X7R, 0603", Cap_Case=0603, Manufacturer="Wurth Elektronik", Supplier Part Number 1=710-885012206087, TempCo=X7R, Tolerance_%=10%, Value1=Unknown, Value2=50V, ValueDisplayed=4700pF
C77_P: library part CMP-0006805-4, "CAP, CERM, 3300 pF, 50 V, +/- 10%, X7R, 0603", Cap_Case=0603, Manufacturer=Wuerth, TempCo=X7R, Tolerance_%=10%, Value1=Unknown, Value2=50V, ValueDisplayed=3300pF
C78_P: library part CMP-0085855-1, "CAP, CERM, 10 µF, 10 V,+/- 10%, X5R, 0603", Cap_Case=0603, Manufacturer=MuRata, TempCo=X5R, Tolerance_%=10%, Value2=10V, ValueDisplayed=10µF
C91_P: library part CMP-0006834-5, "CAP, CERM, 470 pF, 50 V, +/- 10%, X7R, 0603", Cap_Case=0603, Manufacturer="Wurth Elektronik", Supplier Part Number 1=710-885012206081, TempCo=X7R, Tolerance_%=10%, Value1=Unknown, Value2=50V, ValueDisplayed=470pF
C95: library part CMP-0008918-2, "CAP, CERM, 2200 pF, 1000 V, +/- 10%, X7R, 1206", Cap_Case=1206, Manufacturer=MuRata, Supplier Part Number 1=490-3496-1-ND, TempCo=X7R, Tolerance_%=10%, Value1=Unknown, Value2=1000V, ValueDisplayed=2200pF
C96: library part CMP-0007139-2, "CAP, CERM, 1 uF, 25 V, +/- 10%, X7R, AEC-Q200 Grade 1, 0603", Cap_Case=0603, Manufacturer=MuRata, Supplier Part Number 1=490-10673-1-ND, TempCo=X7R, Tolerance_%=10%, Value1=Unknown, Value2=25V, ValueDisplayed=1uF
C97: library part CMP-0007402-2, "CAP, CERM, 1000 pF, 25 V, +/- 10%, X7R, 0603", Cap_Case=0603, Manufacturer=MuRata, Supplier Part Number 1=GRM188R71E102KA01D-ND, TempCo=X7R, Tolerance_%=10%, Value1=Unknown, Value2=25V, ValueDisplayed=1000pF
C98: library part CMP-0091480-1, "0603 0.22 uF 16 V ±10 % Tolerance X7R SMT Multilayer Ceramic Capacitor", Digikey Part Number=311-1426-1-ND, Manufacturer=Yageo, Mouser Part Number=603-CC603KRX7R7BB224, Operating Temperature Range="-55°C to +125°C", TempCo=15%, Temperature Characteristic=X7R, Tolerance_%=10%, ValueDisplayed=220nF, Voltage=16V
C99 C100 C109: library part CMP-0007404-4, "CAP, CERM, 0.1 uF, 25 V, +/- 10%, X7R, 0603", Cap_Case=0603, Manufacturer=MuRata, Supplier Part Number 1=490-1524-1-ND, TempCo=X7R, Tolerance_%=10%, Value1=Unknown, Value2=25V, ValueDisplayed=0.1uF
C108: library part CMP-0083856-1, "CAP, CERM, 1 µF, 25 V,+/- 10%, X7R, 0603", Cap_Case=0603, Manufacturer=TDK, TempCo=X7R, Tolerance_%=10%, Value2=25V, ValueDisplayed=1µF
C110 C111: library part CMP-0080062-1, "CAP, CERM, 47 pF, 50 V,+/- 5%, C0G/NP0, AEC-Q200 Grade 0, 0603", Cap_Case=0603, Manufacturer=TDK, Supplier Part Number 1=445-12417-1-ND, TempCo=C0G/NP0, Tolerance_%=5%, Value2=50V, ValueDisplayed=47pF
C114 C115 C138 C139 C160 C161: library part CMP-0082267-1, "CAP, CERM, 22 µF, 25 V,+/- 10%, X7R, 1210", Cap_Case=1210, Manufacturer=Yageo, Supplier Part Number 1=311-2032-2-ND, TempCo=X7R, Tolerance_%=10%, Value1="0.001 ohm", Value2=25V, ValueDisplayed=22µF
C116 C140 C162 C167: library part CMP-0006720-2, "CAP, CERM, 0.1 uF, 25 V, +/- 20%, X7R, 0402", Cap_Case=0402, Manufacturer="Taiyo Yuden", TempCo=X7R, Tolerance_%=20%, Value1=Unknown, Value2=25V, ValueDisplayed=0.1uF
C117 C118 C119 C120 C121 C122 C123 C124 C125 C126 C127 C128 C800: library part CMP-06035-045930-1, "Multi-Layer Ceramic Capacitor 100nF 16V X5R ±10% 0201 Paper T/R GRT033R61C104KE01D"
C129 C130 C134: library part CMP-06035-015284-1, "Chip Multilayer Ceramic Capacitors for General Purpose, 0402, 1.0uF, X5R, 15%, 20%, 35V GRM155R6YA105ME11D", Capacitance=1uF, Case/Package=0402, Case Code (Metric)=1005, Dielectric=X5R, Max Operating Temperature=85°C, Min Operating Temperature=-55°C, Package Quantity=10000, Tolerance=20%, Voltage Rating=35V
C131: library part CMP-08246-004934-1, "Multilayer Ceramic Capacitors 47pF ±10% 50V C0G SMD 0201 C0603C0G1H470K030BA", Capacitance=47pF, Case/Package=0201, Case Code (Metric)=0603, Dielectric=C0G, Dielectric Material=Ceramic, Max Operating Temperature=125°C, Min Operating Temperature=-55°C, Package Quantity=1, Tolerance=10%, Voltage Rating=50V
C132: library part CMP-06035-031599-1, "Chip Multilayer Ceramic Capacitors for General Purpose, 0402, 2.2uF, X5R, 15%, 10%, 35V GRM155R6YA225KE11D", Case/Package=0402
C133: library part CMP-0008620-2, "CAP, CERM, 3.9 uF, 16 V, +/- 10%, X5R, 1206", Cap_Case=1206, Manufacturer=Kemet, TempCo=X5R, Tolerance_%=10%, Value1="0.012 ohm", Value2=16V, ValueDisplayed=3.9uF
C141: library part CMP-1033-00642-2, "CAP CER 10000PF 16V 10% X5R 0201 C0201C103K4PACTU", Capacitance="10,000 pF", Manufacturer=KEMET, Manufacturer Part Number=C0201C103K4PACTU, Package=C0201-AB, Temperature="-55°C to +125°C", Temperature Characteristic=X5R, Temperature Coefficient=30ppm/°C, Temperature Range High=+125°C, Temperature Range Low=-55°C, Tolerance=0.1, Voltage Rating="16 V"
C146: library part CMP-0006580-2, "CAP, CERM, 0.47 uF, 10 V, +/- 10%, X5R, 0402", Cap_Case=0402, Manufacturer=MuRata, Supplier Part Number 1=490-3264-1-ND, TempCo=X5R, Tolerance_%=10%, Value1=Unknown, Value2=10V, ValueDisplayed=0.47uF
C147 C148: library part CMP-08246-004279-1, "Multilayer Ceramic Capacitors 6pF ±0.5pF 50V NP0 SMD 0603", Capacitance=6pF, Case/Package=0603, Case Code (Metric)=1608, Dielectric=C0G, Max Operating Temperature=150°C, Min Operating Temperature=-55°C, Package Quantity=4000, Voltage Rating=50V
C149 C152 C154: library part CMP-06035-061139-1, "Chip Multilayer Ceramic Capacitors for General Purpose, 0402, 10uF, X5R, 15%, 20%, 6.3V"
C150 C153 C155: library part CMP-2008-02981-1, "04026C104MAT2A", Manufacturer="AVX Interconnect / Elco"
C151: library part CMP-0006853-4, "CAP, CERM, 0.01 uF, 16 V, +/- 10%, X7R, 0603", Cap_Case=0603, Manufacturer=Kemet, Supplier Part Number 1=399-7841-1-ND, TempCo=X7R, Tolerance_%=10%, Value1=Unknown, Value2=16V, ValueDisplayed=0.01uF
C156 C158 C163 C165: library part CMP-0007081-2, "CAP, CERM, 1000 pF, 100 V, +/- 10%, X7R, AEC-Q200 Grade 1, 0603", Cap_Case=0603, Manufacturer=TDK, Supplier Part Number 1=445-5806-1-ND, TempCo=X7R, Tolerance_%=10%, Value1="1.97137 ohm", Value2=100V, ValueDisplayed=1000pF
C157 C164: library part CMP-0006860-5, "CAP, CERM, 0.1 uF, 16 V, +/- 10%, X7R, 0603", Cap_Case=0603, Manufacturer=Kemet, Supplier Part Number 1=399-1096-1-ND, TempCo=X7R, Tolerance_%=10%, Value1=Unknown, Value2=16V, ValueDisplayed=0.1uF
C159 C166: library part CMP-0094642-1, "470 pF ±10% 400V Ceramic Capacitor Y5U (E) Radial, Disc", Digikey Part Number=3487-Q07E1D471KN0B0S0N0-ND, Manufacturer="Songtian Electronic", Operating Temperature Range="-25°C to +125°C", TempCo=-56/+22%, Temperature Characteristic=Y5U, Tolerance_%=10%, ValueDisplayed=470pF, Voltage Ac Rating X=400V
C200_P: library part CMP-0006893-4, "CAP, CERM, 220 pF, 50 V, +/- 5%, C0G/NP0, 0603", Cap_Case=0603, Manufacturer=Kemet, Supplier Part Number 1=399-1066-1-ND, TempCo=C0G/NP0, Tolerance_%=5%, Value1=Unknown, Value2=50V, ValueDisplayed=220pF
D1_P D3_P D5_P D8_P: library part CMP-0028526-2, "Diode, Schottky, 40 V, 0.5 A, SOD-123", Manufacturer="ON Semiconductor", Value1=0.5A, Value2=0.51V
D2_P D7_P D15_P: library part CMP-0028981-2, "Diode, Schottky, 200 V, 1 A, SMA", Manufacturer="Micro Commercial Components", Value1=1A, Value2=0.92V
D4_P D10_P: library part CMP-0029252-2, "Diode, Switching-Bridge, 1000 V, 2.2 A, 8.25x6.6mm", Manufacturer="Micro Commercial Components", Supplier Part Number 1=TBS22M-TPMSCT-ND, Value1=2.2A, Value2=1.1V
D6_P: library part CMP-0085439-1, "Diode, TVS, Uni, 130 V, 209 Vc, 1500 W, 7.5 A, SMC", Manufacturer=STMicroelectronics, Value1=209V
D9_P D34: library part CMP-0076882-1, "Diode, Ultrafast, 1000 V, 1 A, SMA", Manufacturer="Diodes Inc.", Supplier Part Number 1=US1M-FDICT-ND, Value1=1A, Value2=1.7V
D11_P D30_P D33_P: library part CMP-0002935-3, "LED, Green, SMD", Color=Green, Manufacturer="Wurth Elektronik", Power_TotalModule=72mW, Value1=0.072W, Value2=2V
D12_P: library part CMP-0077026-2, "Diode, Ultrafast, 400 V, 1 A, SMA", Manufacturer="Diodes Inc.", Value1=1A, Value2=1.3V
D13_P: library part CMP-0028613-2, "Diode, Schottky, 30 V, 0.2 A, SOT-23", Manufacturer="ON Semiconductor", Value1=0.2A, Value2=0.8V
D14_P D17_P D18_P D23_P D29_P: library part CMP-0029150-2, "Diode, Switching, 200 V, 0.2 A, AEC-Q101, SOD-323", Manufacturer="ON Semiconductor", Value1=0.2A, Value2=1.25V
D16_P: library part CMP-0005844-3, "Diode, Zener, 43 V, 200 mW, SOD-323", Manufacturer="Vishay General Semiconductor", Power_W=200mW, Value1=0.2W
D19_P: library part CMP-0002935-3, "LED, Amber, SMD", Color=Amber, Manufacturer="Wurth Elektronik", Power_TotalModule=72mW, Value1=0.072W, Value2=2V
D20_P D22_P: library part CMP-0028777-2, "Diode, Schottky, 40 V, 2 A, SOD-123FL", Manufacturer="Panjit International Inc.", Value1=2A, Value2=0.63V
D21_P D24_P: library part CMP-0076928-2, "Diode, Schottky, 40 V, 0.35 A, SOD-323", Manufacturer="Micro Commercial Components", Value1=0.35A, Value2=0.6V
D25_P: library part CMP-0085759-1, "Diode, Zener, 16 V, 300 mW, AEC-Q101, SOD-323", Manufacturer="ON Semiconductor", Power_W=300mW, Value1=0.3W
D26_P: library part CMP-0005865-3, "Diode, Zener, 5.1 V, 200 mW, SOD-323", Manufacturer="Diodes Inc.", Power_W=200mW, Value1=0.2W
D27_P D31_P: library part CMP-0002935-3, "LED, Red, SMD", Color=Red, Manufacturer="Wurth Elektronik", Power_TotalModule=72mW, Value1=0.072W, Value2=2V
D28_P: library part CMP-0085006-1, "Diode, TVS, Bi, 15 V, 24.4 Vc, 400 W, 16.4 A, SMA (non-polarized)", Manufacturer=Littelfuse, Value1=24.4V
D32_P: library part CMP-0028529-2, "Diode, Schottky, 40 V, 2 A, SMB", Manufacturer="ON Semiconductor", Value1=2A, Value2=0.43V
D35: library part CMP-0095193-1, "ESD Suppressor Diode TVS Bi-Dir 15V Automotive 2-Pin SOD-323 T/R", Breakdown Voltage=16V, Clamping Voltage=37.5V, Digikey Part Number=F10401CT-ND, Manufacturer=Littelfuse, Mouser Part Number=576-AQ4023-01FTG-C, Operating Temperature Range="-40°C to +150°C", ValueDisplayed=1.3pF
D45 D46: library part CMP-07163-000008-1, "DIODE GEN PURP 75V 200MA SOD523F", Capacitance=4pF, Forward Current=300mA, Manufacturer="ON Semiconductor", Max Junction Temp=+150°C, Max Repetitive Reverse Voltage=75V, Package=502-01, Peak Reverse Current=5uA, Reverse Voltage=100V, Temperature="-55°C to +150°C", Temperature Range Low=-55°C
D47 D48 D49 D50: library part CMP-0029231-3, "Diode, Switching-Bridge, 600 V, 1 A, MICRODIP_4", Manufacturer="Fairchild Semiconductor", Value1=1A, Value2=1.1V
D51 D52 D53 D54 D55: library part CMP-0002905-2, "LED, Green, SMD", Color=Green, Manufacturer="Wurth Elektronik", Value1=W, Value2=3.2V
D200_P D201_P: library part CMP-0085747-1, "Diode, Zener, 7.5 V, 300 mW, SOD-323", Manufacturer="ON Semiconductor", Power_W=300mW, Value1=0.3W
D800 D801 D802 D803: library part CMP-0029148-2, "Diode, Ultrafast, 600 V, 1 A, SOD-123FL", Manufacturer="Micro Commercial Components", Value1=1A, Value2=1.7V
F1_P F2_P F3_P: library part CMP-0003467-2, "Fuse, 1 A, 250VAC/VDC, SMD", Irating_A=1A, Manufacturer=Littelfuse, Supplier Part Number 1=F2906CT-ND
F4 F5: library part CMP-0003461-2, "Fuse, 1.5 A, 50VAC/VDC, SMD", Irating_A=1.5A, Manufacturer=Littelfuse, Supplier Part Number 1=F1611TR-ND
FID1 FID2 FID3: library part CMP-0077181-1, "Fiducial mark.  There is nothing to buy or mount.", Manufacturer=N/A
H1 H2 H3 H4 H5 H6: library part CMP-0003617-1, "Machine Screw, Round, #4-40 x 1/4, Nylon, Philips panhead", Manufacturer="B&F Fastener Supply", Supplier Part Number 1=H542-ND
J1_P: library part CMP-0054825-2, "Terminal Block, 3.5mm, 2x1, Tin, TH", Color=Green, Current_A=10A, Manufacturer="Wurth Elektronik", Supplier Part Number 1=732-2747-ND, Voltage_V=300V
J2: library part CMP-0095404-1, Current_A=3.4A, Digikey Part Number=SAM10516-ND, Manufacturer=Samtec, Mouser Part Number=200-FTSH12001LD, Operating Temperature Range="-55°C to +125°C"
J3: library part CMP-0086014-1, "Header, 2.54mm, 7x2, Gold, TH", Color=Black, Current_A=3A, Manufacturer="Wurth Elektronik", Voltage_V=250V
J4: library part CMP-0054829-1, "Terminal Block, 5 mm, 3x1, Tin, TH", Manufacturer="Wurth Elektronik", Supplier Part Number 1=732-2027-ND
J15: library part CMP-0054828-1, "Terminal Block, 5 mm, 2x1, Tin, TH", Manufacturer="Wurth Elektronik", Supplier Part Number 1=732-2026-ND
